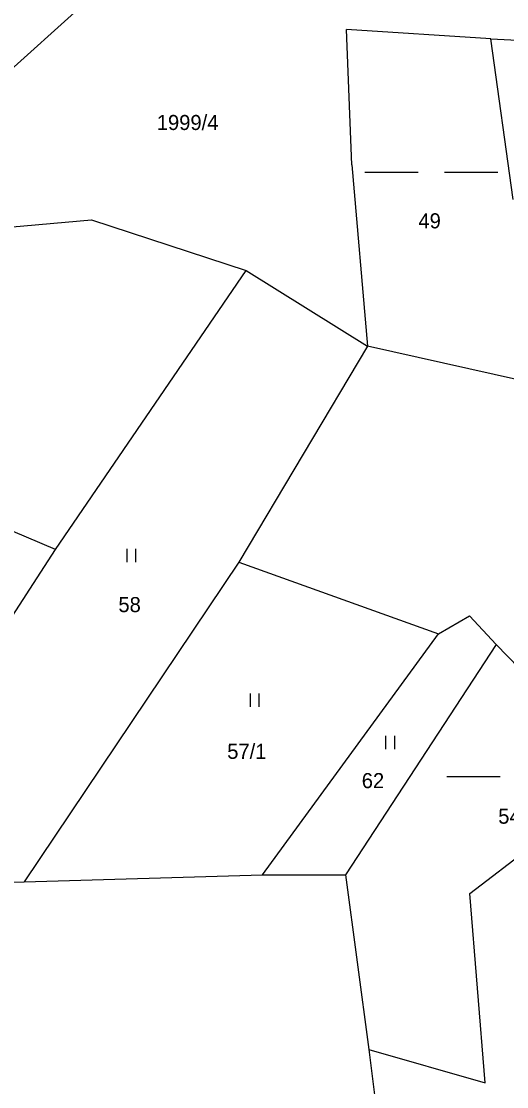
# Model space of a CAD drawing. Extents: x -820420 to -815896, y -1105820 to -1103643.
# Drawn here: x -817814 to -817759.2, y -1104849.8 to -1104729.7 of the extents above; entities that cross this region are included whole.
import ezdxf
from ezdxf.enums import TextEntityAlignment as Align

# ---------------------------------------------------------------- set-up
doc = ezdxf.new("R2010")
doc.units = 0
doc.header["$LTSCALE"] = 0.68
doc.layers.add('1', color=7, linetype='Continuous', lineweight=25)
doc.layers.add('3', color=7, linetype='Continuous', lineweight=25)
doc.layers.add('2', color=7, linetype='Continuous')

msp = doc.modelspace()

# ---------------------------------------------------------------- linework, layer by layer
at = {"layer": '1'}
for p, q in [((-817806.46, -1104727.35), (-817831.84, -1104750.1)), ((-817776.7, -1104745.88), (-817777.32, -1104730.6)), ((-817761.01, -1104731.66), (-817777.32, -1104730.6)), ((-817758.5, -1104749.79), (-817761.01, -1104731.66)), ((-817761.01, -1104731.66), (-817754.69, -1104731.98)), ((-817776.7, -1104745.88), (-817774.92, -1104766.31)), ((-817825.65, -1104753.8), (-817806.06, -1104752.09)), ((-817806.06, -1104752.09), (-817788.61, -1104757.79)), ((-817810.13, -1104789.27), (-817788.61, -1104757.79)), ((-817788.61, -1104757.79), (-817774.92, -1104766.31)), ((-817774.92, -1104766.31), (-817789.43, -1104790.69)), ((-817757.8, -1104770.17), (-817774.92, -1104766.31)), ((-817810.13, -1104789.27), (-817843.22, -1104775.07)), ((-817816.86, -1104799.64), (-817810.13, -1104789.27)), ((-817789.43, -1104790.69), (-817813.66, -1104826.75)), ((-817789.43, -1104790.69), (-817766.93, -1104798.75)), ((-817766.93, -1104798.75), (-817763.43, -1104796.75)), ((-817763.43, -1104796.75), (-817760.41, -1104799.96)), ((-817786.76, -1104825.95), (-817766.93, -1104798.75)), ((-817760.41, -1104799.96), (-817777.43, -1104825.95)), ((-817760.41, -1104799.96), (-817755.07, -1104805.53)), ((-817763.38, -1104828.05), (-817754.75, -1104821.41)), ((-817834.95, -1104827.02), (-817813.66, -1104826.75)), ((-817813.66, -1104826.75), (-817786.76, -1104825.95)), ((-817786.76, -1104825.95), (-817777.43, -1104825.95)), ((-817777.43, -1104825.95), (-817774.8, -1104845.65)), ((-817761.65, -1104849.4), (-817763.38, -1104828.05)), ((-817774.8, -1104845.65), (-817773.03, -1104859.23)), ((-817774.8, -1104845.65), (-817761.65, -1104849.4))]:
    msp.add_line(p, q, dxfattribs=at)
at = {"layer": '3'}
for p, q in [((-817775.239, -1104746.71), (-817769.239, -1104746.71)), ((-817766.239, -1104746.71), (-817760.239, -1104746.71)), ((-817802.041, -1104790.68), (-817802.041, -1104789.18)), ((-817801.04, -1104790.68), (-817801.04, -1104789.18)), ((-817788.141, -1104807.01), (-817788.141, -1104805.51)), ((-817787.14, -1104807.01), (-817787.14, -1104805.51)), ((-817772.871, -1104811.76), (-817772.871, -1104810.26)), ((-817771.87, -1104811.76), (-817771.87, -1104810.26)), ((-817765.979, -1104814.85), (-817759.979, -1104814.85))]:
    msp.add_line(p, q, dxfattribs=at)

# ---------------------------------------------------------------- texts
at = {"layer": '2'}
for s, p in [('1999/4', (-817795.22, -1104741.945)), ('49', (-817767.929, -1104753.035)), ('58', (-817801.759, -1104796.315)), ('57/1', (-817788.539, -1104812.865)), ('62', (-817774.319, -1104816.165)), ('54', (-817758.929, -1104820.175))]:
    msp.add_text(s, height=1.7, dxfattribs=at).set_placement(p, align=Align.CENTER)

doc.saveas('drawing.dxf')
